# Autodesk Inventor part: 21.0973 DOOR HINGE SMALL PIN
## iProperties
Created: 2010-07
Part Number: 21.0973 DOOR HINGE SMALL PIN
Document SubType Name: Modeling
Designer: Administrator
Density: 1 g/cm^3
Author: Administrator
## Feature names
1. Extrusion1
2. Chamfer1
